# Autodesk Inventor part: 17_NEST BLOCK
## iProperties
Created: 2006-12
Part Number: 17_NEST BLOCK
Document SubType Name: Modeling
Designer: RDGodetteII
Density: 1 g/cm^3
Author: RDGodetteII
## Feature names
1. Extrusion1
2. Hole1
3. Rectangular Pattern1
